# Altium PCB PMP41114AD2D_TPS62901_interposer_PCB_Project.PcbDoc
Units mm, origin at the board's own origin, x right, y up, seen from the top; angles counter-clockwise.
Board outline 10 x 15 mm, 2 copper layers (Top Layer, Bottom Layer), stack 1.575 mm thick; 10 components, 8 nets, 27 pads, 6 vias.
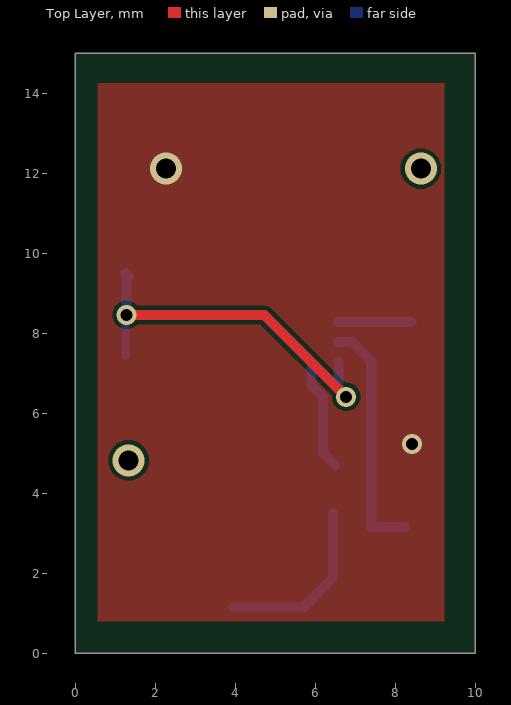
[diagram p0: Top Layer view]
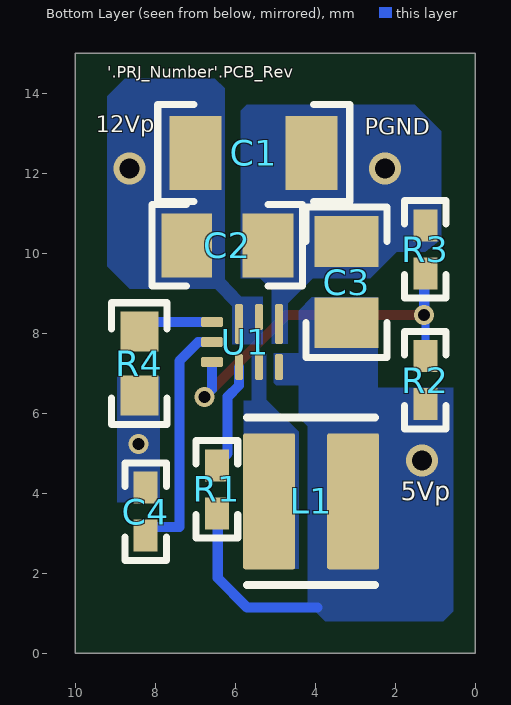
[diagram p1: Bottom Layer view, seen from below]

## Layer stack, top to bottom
Top Solder: solder mask 0.0102, Solder Resist, Dk 3.5
Top Layer: signal copper 0.0356
Dielectric1: core 1.5037, FR-4 High Tg, Dk 4.8
Bottom Layer: signal copper 0.0356
Bottom Solder: solder mask 0.0102, Solder Resist, Dk 3.5

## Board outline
0,0 0,15 10,15 10,0

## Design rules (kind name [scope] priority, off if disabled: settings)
AcuteAngle [All] p1: minimum=4.50000000000000E+0001 checktracksonly=FALSE
AssemblyTestPointUsage [All] p1: valid=2
BoardOutlineClearance [All] p1: gap=0.15 ignorepadtopadclearanceinfootprint=FALSE
Clearance Clearance_3 [All] p1: gap=0.1 ignorepadtopadclearanceinfootprint=FALSE
Clearance Clearance_2 [InNetClass('HV') vs InNetClass('HV')] p2: gap=1 ignorepadtopadclearanceinfootprint=TRUE
Clearance Clearance_1 [InNetClass('MV') vs Not InNetClass('MV')] p3: gap=0.2 ignorepadtopadclearanceinfootprint=TRUE
Clearance Clearance_Keepouts [((IsTrack Or IsArc) And Not InPoly) And IsFree and IsKeepOut vs ((IsTrack Or IsArc) And Not InPoly) And IsFree and IsKeepOut] p4: gap=0.3 ignorepadtopadclearanceinfootprint=FALSE
Clearance Clearance_BoardEdge_MountingHoles [OnCopper and InComponentClass('Mounting Holes') vs IsKeepOut] p5: gap=0.3 ignorepadtopadclearanceinfootprint=FALSE
Clearance Clearance_BoardEdge_Poly [OnCopper and InPoly vs IsKeepOut] p6: gap=0.635 ignorepadtopadclearanceinfootprint=FALSE except(0: Arc-Hole Track-Hole SMDPad-Hole THPad-Hole Via-Hole Fill-Hole Poly-Hole Region-Hole Text-Hole)
Clearance Clearance_BoardEdge [OnCopper and Not InComponentClass('Logo') and not InComponentClass('FiducialMark') and not InRegion(1000,500,4000,800) and Not IsKeepout vs IsKeepOut] p7: gap=1.905 ignorepadtopadclearanceinfootprint=FALSE except(0: Arc-Hole Track-Hole SMDPad-Hole THPad-Hole Via-Hole Fill-Hole Poly-Hole Region-Hole Text-Hole)
Clearance Clearance_Poly [InPolygon] p8: gap=0 ignorepadtopadclearanceinfootprint=FALSE
Clearance [All] p9: gap=0.2 ignorepadtopadclearanceinfootprint=FALSE except(0: Arc-SMDPad Arc-Hole Track-Hole SMDPad-Hole THPad-Hole Via-Hole Fill-Hole Poly-Hole Region-Hole Text-Hole; 0.1: Arc-Via Track-Via SMDPad-Via THPad-Via Via-Via; 0.127: Arc-Arc Arc-Track Arc-THPad Arc-Fill Track-Track Track-SMDPad Track-THPad Track-Fill SMDPad-SMDPad SMDPad-THPad SMDPad-Fill THPad-THPad THPad-Fill Via-Fill Fill-Fill)
ComponentClearance ComponentClearance_MountingHoles_FiducialMarks [InComponentClass('Mounting Holes') vs InComponentClass('FiducialMark')] p1: gap=0.508 collisioncheckmode=3 verticalgap=0.178 showdistances=FALSE
ComponentClearance ComponentClearance_Shunt [InComponentClass('Header') vs InComponentClass('Shunt')] p2: gap=0 collisioncheckmode=3 verticalgap=0 showdistances=FALSE
ComponentClearance ComponentClearance_Logo [InComponentClass('Logo')] p3: gap=0.127 collisioncheckmode=3 verticalgap=0.254 showdistances=FALSE
ComponentClearance ComponentClearance_ScrewToNut [(HasFootprint('KEYSTONE_4824')) vs (HasFootprint('Keystone_1903C'))] p4: gap=0 collisioncheckmode=3 verticalgap=0 showdistances=FALSE
ComponentClearance ComponentClearance_MountingHoles [InComponentClass('Mounting Holes')] p5: gap=0.508 collisioncheckmode=3 verticalgap=0.178 showdistances=FALSE
ComponentClearance ComponentClearance_SmallPassives [HasFootprint('0201*') or HasFootprint('0402*') or HasFootprint('0508') or HasFootprint('0603*') or HasFootprint('0612') or HasFootprint('0805*') or HasFootprint('0815*') or HasFootprint('0830*') or HasFootprint('1206*') or HasFootprint('1210*') or HasFootprint('1808*') or HasFootprint('1812*') or HasFootprint('1825*') or HasFootprint('2010*') or HasFootprint('2220*') or HasFootprint('2225*') or HasFootprint('2512*') or HasFootprint('2728*') or HasFootprint('3518*') vs HasFootprint('0201*') or HasFootprint('0402*') or HasFootprint('0508') or HasFootprint('0603*') or HasFootprint('0612') or HasFootprint('0805*') or HasFootprint('0815*') or HasFootprint('0830*') or HasFootprint('1206*') or HasFootprint('1210*') or HasFootprint('1808*') or HasFootprint('1812*') or HasFootprint('1825*') or HasFootprint('2010*') or HasFootprint('2220*') or HasFootprint('2225*') or HasFootprint('2512*') or HasFootprint('2728*') or HasFootprint('3518*')] p6: gap=0.127 collisioncheckmode=3 verticalgap=0.025 showdistances=FALSE
ComponentClearance ComponentClearance_THtoSMT [IsThruComponent vs IsSMTComponent] p7: gap=0.254 collisioncheckmode=3 verticalgap=0.178 showdistances=FALSE
ComponentClearance ComponentClearance_THtoTH [IsThruComponent vs IsThruComponent] p8: gap=0.254 collisioncheckmode=3 verticalgap=0.178 showdistances=FALSE
ComponentClearance [All] p9: gap=0.254 collisioncheckmode=3 verticalgap=0.178 showdistances=FALSE
DiffPairsRouting [All] p1: maxlimit=2.54 minlimit=0.254 mostfreqgap=0.254 toplayer_minwidth=0.381 toplayer_maxwidth=0.381 toplayer_prefwidth=0.381 bottomlayer_minwidth=0.381 bottomlayer_maxwidth=0.381 bottomlayer_prefwidth=0.381 maxuncoupledlength=25.4
FabricationTestPointUsage TestPointUsage [All] p1: valid=2 allowmultiple=FALSE
FabricationTestpoint Testpoint [All] p1: side=3 testpointundercomponent=TRUE minsize=1.016 maxsize=2.54 preferedsize=1.524 minholesize=0 maxholesize=1.016 preferedholesize=0.813 testpointgrid=0.025 allowsidetop=TRUE allowsidebottom=TRUE usegrid=TRUE gridtolerance=0
FanoutControl Fanout_LCC [IsLCC] p1: bgadir=Out bgaviamode=Centered fanoutstyle=Auto fanoutdirection=Alternating viagrid=0.025 // Fanout_LCC (Default Rule)
FanoutControl Fanout_BGA [IsBGA] p2: bgadir=Out bgaviamode=Centered fanoutstyle=Auto fanoutdirection=Alternating viagrid=0.025 // Fanout_BGA (Default Rule)
Height [All] p1: minheight=0 maxheight=76.2 prefheight=12.7
HoleSize [All] p1: absolutevalues=TRUE maxlimit=12.725 minlimit=0.178 maxpercent=80.000 minpercent=20.000
MinimumAnnularRing MinimumAnnularRing_ThermalPadVias [IsVia and InAnyComponent] p1: minimumring=0.15
MinimumAnnularRing [All] p2: minimumring=0.127
MinimumSolderMaskSliver MinimumSolderMaskSliver_Logo [InComponentClass('Logo') vs InComponentClass('Logo')] p1: minsoldermaskwidth=0.018
MinimumSolderMaskSliver [All] p2: minsoldermaskwidth=0.018
PlaneClearance [All] p1: clearance=0.2
PlaneConnect [All] p1: planeconnectstyle=Direct reliefexpansion=0.254 reliefentries=4 reliefconductorwidth=0.254 reliefairgap=0.254
PolygonConnect PolygonConnect_16 [All vs IsNamedPolygon('C106_2') Or IsNamedPolygon('Vout') Or IsNamedPolygon('IN+') Or IsNamedPolygon('Q203_5') Or IsNamedPolygon('IN+') Or IsNamedPolygon('Q201_5') Or IsNamedPolygon('C108_2') Or IsNamedPolygon('SGND') Or IsNamedPolygon('IN+') Or IsNamedPolygon('SGND') Or IsNamedPolygon('Q203_5') Or IsNamedPolygon('IN+') Or IsNamedPolygon('SGND') Or IsNamedPolygon('GND') Or IsNamedPolygon('C113_2') Or IsNamedPolygon('C107_2') Or IsNamedPolygon('C107_2') Or IsNamedPolygon('Vout') Or IsNamedPolygon('SIGNAL_LAYER_1_GND_P074') Or IsNamedPolygon('HV') Or IsNamedPolygon('C108_2') Or IsNamedPolygon('C103_2') Or IsNamedPolygon('Q201_5') Or IsNamedPolygon('Vout') Or IsNamedPolygon('C109_2') Or IsNamedPolygon('Q201_5') Or IsNamedPolygon('GND') Or IsNamedPolygon('C107_2') Or IsNamedPolygon('C102_1') Or IsNamedPolygon('GND') Or IsNamedPolygon('SGND') Or IsNamedPolygon('HS') Or IsNamedPolygon('Q203_5') Or IsNamedPolygon('Q201_5') Or IsNamedPolygon('Q203_5')] p1: connectstyle=Direct reliefconductorwidth=0.254 reliefentries=4 polygonreliefangle="90 Angle" airgapwidth=0.254
PolygonConnect PolygonConnect_15 [All vs IsNamedPolygon('C109_2') Or IsNamedPolygon('C107_2') Or IsNamedPolygon('HV') Or IsNamedPolygon('Q203_5') Or IsNamedPolygon('C107_2') Or IsNamedPolygon('HS') Or IsNamedPolygon('Q201_5') Or IsNamedPolygon('Q203_5') Or IsNamedPolygon('C106_2') Or IsNamedPolygon('C108_2') Or IsNamedPolygon('Vout') Or IsNamedPolygon('Q203_5') Or IsNamedPolygon('C108_2') Or IsNamedPolygon('C113_2') Or IsNamedPolygon('Q203_5') Or IsNamedPolygon('Q201_5') Or IsNamedPolygon('C107_2') Or IsNamedPolygon('C102_1') Or IsNamedPolygon('SGND') Or IsNamedPolygon('GND') Or IsNamedPolygon('SGND') Or IsNamedPolygon('GND') Or IsNamedPolygon('IN+') Or IsNamedPolygon('IN+') Or IsNamedPolygon('Q201_5') Or IsNamedPolygon('Q201_5') Or IsNamedPolygon('SGND') Or IsNamedPolygon('SGND') Or IsNamedPolygon('Vout') Or IsNamedPolygon('Vout') Or IsNamedPolygon('IN+') Or IsNamedPolygon('GND') Or IsNamedPolygon('IN+') Or IsNamedPolygon('GND')] p2: connectstyle=Direct reliefconductorwidth=0.254 reliefentries=4 polygonreliefangle="90 Angle" airgapwidth=0.254
PolygonConnect PolygonConnect_14 [All vs IsNamedPolygon('C106_2') Or IsNamedPolygon('C107_2') Or IsNamedPolygon('C107_2') Or IsNamedPolygon('C107_2') Or IsNamedPolygon('C102_1') Or IsNamedPolygon('Q203_5') Or IsNamedPolygon('Vout') Or IsNamedPolygon('Q203_5') Or IsNamedPolygon('Q203_5') Or IsNamedPolygon('Q201_5') Or IsNamedPolygon('C108_2') Or IsNamedPolygon('Q203_5') Or IsNamedPolygon('HS') Or IsNamedPolygon('HV') Or IsNamedPolygon('C108_2') Or IsNamedPolygon('Q201_5') Or IsNamedPolygon('C109_2') Or IsNamedPolygon('Q201_5') Or IsNamedPolygon('Q201_5') Or IsNamedPolygon('C113_2')] p3: connectstyle=Direct reliefconductorwidth=0.254 reliefentries=4 polygonreliefangle="90 Angle" airgapwidth=0.254
PolygonConnect PolygonConnect_13 [All vs IsNamedPolygon('C102_1') Or IsNamedPolygon('HV') Or IsNamedPolygon('C107_2') Or IsNamedPolygon('C109_2') Or IsNamedPolygon('C107_2') Or IsNamedPolygon('C108_2') Or IsNamedPolygon('C106_2') Or IsNamedPolygon('C108_2') Or IsNamedPolygon('C113_2') Or IsNamedPolygon('C107_2')] p4: connectstyle=Direct reliefconductorwidth=0.254 reliefentries=4 polygonreliefangle="90 Angle" airgapwidth=0.254
PolygonConnect PolygonConnect_12 [All vs IsNamedPolygon('C107_2') Or IsNamedPolygon('C113_2') Or IsNamedPolygon('C106_2') Or IsNamedPolygon('C107_2') Or IsNamedPolygon('C107_2') Or IsNamedPolygon('C102_1')] p5: connectstyle=Direct reliefconductorwidth=0.254 reliefentries=4 polygonreliefangle="90 Angle" airgapwidth=0.254
PolygonConnect PolygonConnect_11 [All vs IsNamedPolygon('C106_2') Or IsNamedPolygon('C102_1') Or IsNamedPolygon('C107_2') Or IsNamedPolygon('C107_2') Or IsNamedPolygon('C107_2')] p6: connectstyle=Direct reliefconductorwidth=0.254 reliefentries=4 polygonreliefangle="90 Angle" airgapwidth=0.254
PolygonConnect PolygonConnect_10 [All vs IsNamedPolygon('C106_2')] p7: connectstyle=Direct reliefconductorwidth=0.254 reliefentries=4 polygonreliefangle="90 Angle" airgapwidth=0.254
PolygonConnect PolygonConnect_9 [All vs IsNamedPolygon('C11_1') Or IsNamedPolygon('Vin') Or IsNamedPolygon('Vin') Or IsNamedPolygon('5V') Or IsNamedPolygon('D6_2') Or IsNamedPolygon('Q3_3') Or IsNamedPolygon('GND2') Or IsNamedPolygon('GND2') Or IsNamedPolygon('GND') Or IsNamedPolygon('Q3_4') Or IsNamedPolygon('12V5') Or IsNamedPolygon('GND') Or IsNamedPolygon('12V5') Or IsNamedPolygon('D3_1')] p8: connectstyle=Direct reliefconductorwidth=0.254 reliefentries=4 polygonreliefangle="90 Angle" airgapwidth=0.254
PolygonConnect PolygonConnect_8 [All vs IsNamedPolygon('C11_1') Or IsNamedPolygon('Vin') Or IsNamedPolygon('12V5') Or IsNamedPolygon('Q3_3') Or IsNamedPolygon('GND2') Or IsNamedPolygon('GND2') Or IsNamedPolygon('5V') Or IsNamedPolygon('Q3_4') Or IsNamedPolygon('12V5')] p9: connectstyle=Direct reliefconductorwidth=0.254 reliefentries=4 polygonreliefangle="90 Angle" airgapwidth=0.254
PolygonConnect PolygonConnect_7 [All vs IsNamedPolygon('GND2') Or IsNamedPolygon('GND2') Or IsNamedPolygon('5V') Or IsNamedPolygon('12V5') Or IsNamedPolygon('12V5') Or IsNamedPolygon('C11_1')] p10: connectstyle=Direct reliefconductorwidth=0.254 reliefentries=4 polygonreliefangle="90 Angle" airgapwidth=0.254
PolygonConnect PolygonConnect_6 [All vs IsNamedPolygon('GND2') Or IsNamedPolygon('SGND') Or IsNamedPolygon('GND1') Or IsNamedPolygon('C901_1') Or IsNamedPolygon('SGND') Or IsNamedPolygon('GND2') Or IsNamedPolygon('GND1')] p11: connectstyle=Direct reliefconductorwidth=0.254 reliefentries=4 polygonreliefangle="90 Angle" airgapwidth=0.254
PolygonConnect PolygonConnect_5 [All vs IsNamedPolygon('GND1') Or IsNamedPolygon('GND1')] p12: connectstyle=Direct reliefconductorwidth=0.254 reliefentries=4 polygonreliefangle="90 Angle" airgapwidth=0.254
PolygonConnect PolygonConnect_4 [All vs IsNamedPolygon('C21_1') Or IsNamedPolygon('C5_1') Or IsNamedPolygon('C12_2') Or IsNamedPolygon('C2_2') Or IsNamedPolygon('C13_1') Or IsNamedPolygon('C28_1') Or IsNamedPolygon('C6_1') Or IsNamedPolygon('GND') Or IsNamedPolygon('GND2') Or IsNamedPolygon('C14_1') Or IsNamedPolygon('C13_1') Or IsNamedPolygon('Q1_3') Or IsNamedPolygon('C14_1') Or IsNamedPolygon('C5_1') Or IsNamedPolygon('GND2') Or IsNamedPolygon('C28_1') Or IsNamedPolygon('D5_2') Or IsNamedPolygon('D6_2') Or IsNamedPolygon('D2_1') Or IsNamedPolygon('C12_2') Or IsNamedPolygon('D2_1') Or IsNamedPolygon('C4_1') Or IsNamedPolygon('C4_1') Or IsNamedPolygon('C2_2') Or IsNamedPolygon('GND') Or IsNamedPolygon('C33_1') Or IsNamedPolygon('C9_1')] p13: connectstyle=Direct reliefconductorwidth=0.254 reliefentries=4 polygonreliefangle="90 Angle" airgapwidth=0.254
PolygonConnect PolygonConnect_3 [All vs IsNamedPolygon('C28_1') Or IsNamedPolygon('C12_2') Or IsNamedPolygon('C28_1') Or IsNamedPolygon('C9_1') Or IsNamedPolygon('D5_2') Or IsNamedPolygon('C12_2') Or IsNamedPolygon('C2_2') Or IsNamedPolygon('C14_1') Or IsNamedPolygon('C4_1') Or IsNamedPolygon('C14_1') Or IsNamedPolygon('D6_2') Or IsNamedPolygon('GND2') Or IsNamedPolygon('Q1_3') Or IsNamedPolygon('C5_1') Or IsNamedPolygon('D2_1') Or IsNamedPolygon('C4_1') Or IsNamedPolygon('C13_1') Or IsNamedPolygon('C5_1') Or IsNamedPolygon('C13_1') Or IsNamedPolygon('C33_1') Or IsNamedPolygon('D2_1') Or IsNamedPolygon('GND') Or IsNamedPolygon('GND') Or IsNamedPolygon('GND2') Or IsNamedPolygon('C2_2') Or IsNamedPolygon('C6_1') Or IsNamedPolygon('C21_1')] p14: connectstyle=Direct reliefconductorwidth=0.254 reliefentries=4 polygonreliefangle="90 Angle" airgapwidth=0.254
PolygonConnect PolygonConnect_2 [All vs IsNamedPolygon('C21_1') Or IsNamedPolygon('C4_1') Or IsNamedPolygon('D5_2') Or IsNamedPolygon('C5_1') Or IsNamedPolygon('C14_1') Or IsNamedPolygon('C13_1') Or IsNamedPolygon('C4_1') Or IsNamedPolygon('C33_1') Or IsNamedPolygon('C12_2') Or IsNamedPolygon('D2_1') Or IsNamedPolygon('C2_2') Or IsNamedPolygon('C28_1') Or IsNamedPolygon('C12_2') Or IsNamedPolygon('D2_1') Or IsNamedPolygon('C5_1') Or IsNamedPolygon('Q1_3') Or IsNamedPolygon('GND') Or IsNamedPolygon('D6_2') Or IsNamedPolygon('C6_1') Or IsNamedPolygon('C2_2') Or IsNamedPolygon('C14_1') Or IsNamedPolygon('C28_1') Or IsNamedPolygon('C13_1') Or IsNamedPolygon('C9_1') Or IsNamedPolygon('GND')] p15: connectstyle=Direct reliefconductorwidth=0.254 reliefentries=4 polygonreliefangle="90 Angle" airgapwidth=0.254
PolygonConnect PolygonConnect_1 [All vs IsNamedPolygon('C28_1') Or IsNamedPolygon('D5_2') Or IsNamedPolygon('C5_1') Or IsNamedPolygon('C5_1') Or IsNamedPolygon('D2_1') Or IsNamedPolygon('C21_1') Or IsNamedPolygon('C9_1') Or IsNamedPolygon('C4_1') Or IsNamedPolygon('C14_1') Or IsNamedPolygon('C28_1') Or IsNamedPolygon('C6_1') Or IsNamedPolygon('C12_2') Or IsNamedPolygon('C33_1') Or IsNamedPolygon('C4_1') Or IsNamedPolygon('C13_1') Or IsNamedPolygon('C12_2') Or IsNamedPolygon('D6_2') Or IsNamedPolygon('C2_2') Or IsNamedPolygon('C14_1') Or IsNamedPolygon('D2_1') Or IsNamedPolygon('C2_2') Or IsNamedPolygon('C13_1')] p16: connectstyle=Direct reliefconductorwidth=0.254 reliefentries=4 polygonreliefangle="90 Angle" airgapwidth=0.254
PolygonConnect [All] p17: connectstyle=Direct reliefconductorwidth=0.254 reliefentries=4 polygonreliefangle="90 Angle" airgapwidth=0.254
RoutingVias ThermalPadVias [IsVia and not InNet('SGND')and not InNet('Vout')] p1: holewidth=0.2 width=0.5 viastyle="Through Hole" minholewidth=0.2 minwidth=0.5 maxholewidth=1 maxwidth=2
RoutingVias [IsVia and not InNet('SGND')and not InNet('Vout')] p2: holewidth=0.406 width=0.864 viastyle="Through Hole" minholewidth=0.2 minwidth=0.508 maxholewidth=1.016 maxwidth=1.651
SilkToBoardRegionClearance [Not ((IsComment or IsDesignator) And (Hide <> 'False')) and not InRegion(1000,500,4000,800)] p1:
SilkToSilkClearance SilkToSilkClearance_Pb-FreeLogo [(HasFootprint('Pb-Free_Overlay_Medium') OR HasFootprint('Pb-Free_Overlay_Small')) vs (HasFootprint('Pb-Free_Overlay_Medium') OR HasFootprint('Pb-Free_Overlay_Small'))] p1: silktosilkclearance=0
SilkToSilkClearance [All] p2: silktosilkclearance=0
SilkToSolderMaskClearance "Silk to Solder Mask Opening" [All] p1: minsilkscreentomaskgap=0 clearancetoexposedcopper=FALSE
SolderMaskExpansion [All] p1: expansion=0.05 istentingtop=FALSE
SupplyNets "Schematic Supply Nets_1" [InNet('PGND')] p1: voltage=0.000
UnpouredPolygon [All] p1: allowunpoured=TRUE allowshelved=TRUE
Width [All] p1: maxlimit=2.54 minlimit=0.152 preferedwidth=0.2 checkconnectedcopper=TRUE
14 further rules are at their usual default settings.

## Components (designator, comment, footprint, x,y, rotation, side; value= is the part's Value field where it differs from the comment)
C1 "C3216X7R1A106M160AC" 1206 5.54,12.51 r180 bottom value=10uF
C2 "C0805C105K3RACTU" 0805_HV 6.2,10.2 r180 bottom value=1uF
C3 "CL21A226KQQNNNE" 0805_HV 3.22,9.28 r90 bottom value=22uF
C4 "GRM155R72A332KA01D" 0402 8.24,3.54 r90 bottom value=3300pF
L1 "74438336022" FP-74438336010_SMD2-MFG 4.105,3.8 r180 bottom
R1 "RC0402FR-07100KL" 0402 6.46,4.1 r270 bottom value=100k
R2 "RC0402FR-07100KL" 0402 1.25,6.83 r270 bottom value=100k
R3 "CRCW040276K8FKED" 0402 1.25,10.1 r270 bottom value=76.8k
R4 "CRCW0603118KFKEA" 0603 8.4,7.24 r90 bottom value=118k
U1 "TPS62901RPJR" RPJ0009A 5.659,7.781 r90 bottom

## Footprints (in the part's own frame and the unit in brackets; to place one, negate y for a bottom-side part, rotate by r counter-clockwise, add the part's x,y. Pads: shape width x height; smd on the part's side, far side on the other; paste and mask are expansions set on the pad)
0402 [mm] "0402 from SM-752 data"
  rect 0.8x0.6 smd: 1(-0.6,0) 2(0.6,0)
  silkscreen extent -1.22,-0.52 1.22,0.52, body extent -0.55,-0.3 0.55,0.3, height 0.6
0603 [mm] "0603 from SM-752 data"
  rect 1x0.95 smd: 1(-0.8,0) 2(0.8,0)
  silkscreen extent -1.52,-0.69 1.52,0.69, body extent -0.87,-0.47 0.87,0.47, height 1
0805_HV [mil] "0805 with 30mil clearance between pads"
  rect 50x63 smd: 1(-40,0) 2(40,0)
  silkscreen extent -74,-40 74,40, body extent -43,-29 43,29, height 57
1206 [mm] "1206 from SM-752 data"
  rect 1.3x1.85 smd: 1(-1.45,0) 2(1.45,0)
  silkscreen extent -2.4,-1.21 2.4,1.21, body extent -1.7,-0.9 1.7,0.9, height 1.35
FP-74438336010_SMD2-MFG [mm]
  rrect8% 1.3x3.4 smd paste+0 mask+0: 1(-1.05,0) 2(1.05,0)
  silkscreen extent -1.6,-2.1 1.6,2.1, body extent -1.5,-1.5 1.5,1.5, height 2
RPJ0009A [mm] "VQFN-HR-9"
  rrect50% 0.65x0.2 smd: 1(-0.625,0.25) 2(-0.625,-0.25) 3(-0.625,-0.75) 5(0.625,-0.25)
  rrect50% 1x0.2 smd: 4(0.45,-0.75) 6(0.45,0.25)
  rrect40% 0.25x0.55 smd: 7(0.5,0.925) 8(0,0.925) 9(-0.5,0.925)
  body extent -0.8,-1.05 0.8,1.05, height 1

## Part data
C1: library part CMP-0008689-2, "CAP, CERM, 10 uF, 10 V, +/- 20%, X7R, 1206", Cap_Case=1206, Manufacturer=TDK, Supplier Part Number 1=445-1602-1-ND, TempCo=X7R, Tolerance_%=20%, Value1="0.0046 ohm", Value2=10V, ValueDisplayed=10uF
C2: library part CMP-0007728-2, "CAP, CERM, 1 uF, 25 V, +/- 10%, X7R, 0805", Cap_Case=0805, Manufacturer=Kemet, Supplier Part Number 1=399-8004-1-ND, TempCo=X7R, Tolerance_%=10%, Value1=Unknown, Value2=25V, ValueDisplayed=1uF
C3: library part CMP-0007989-2, "CAP, CERM, 22 uF, 6.3 V, +/- 10%, X5R, 0805", Cap_Case=0805, Manufacturer="Samsung Electro-Mechanics", TempCo=X5R, Tolerance_%=10%, Value1=Unknown, Value2=6.3V, ValueDisplayed=22uF
C4: library part CMP-0006708-2, "CAP, CERM, 3300 pF, 100 V, +/- 10%, X7R, 0402", Cap_Case=0402, Manufacturer=MuRata, Supplier Part Number 1=GRM155R72A332KA01D-ND, TempCo=X7R, Tolerance_%=10%, Value1=Unknown, Value2=100V, ValueDisplayed=3300pF
L1: library part CMP-0087867-1, "2.2µH Shielded Molded Inductor 2.4A 67mOhm Max 2-SMD", Manufacturer="Wurth Electronics"
R1 R2: library part CMP-0026721-1, "RES, 100 k, 1%, 0.0625 W, 0402", Manufacturer="Yageo America", Power_W=62.5mW, Supplier Part Number 1=311-100KLRCT-ND, TempCo="100 ppm/C", Tolerance_%=1%, Value2=0.0625W, Value_Code=100k
R3: library part CMP-0026547-2, "RES, 76.8 k, 1%, 0.063 W, AEC-Q200 Grade 0, 0402", Manufacturer=Vishay-Dale, Power_W=63mW, Supplier Part Number 1=541-76.8KLCT-ND, TempCo="100 ppm/C", Tolerance_%=1%, Value2=0.063W, Value_Code=76k8, ValueDisplayed=76.8k
R4: library part CMP-0022014-4, "RES, 118 k, 1%, 0.1 W, AEC-Q200 Grade 0, 0603", Manufacturer=Vishay-Dale, Power_W=100mW, Supplier Part Number 1=541-118KHCT-ND, TempCo="100 ppm/C", Tolerance_%=1%, Value2=0.1W, Value_Code=118k
U1: library part CMP-0084864-4, "2.9-V to 18-V, 4-A Synchronous Buck Converters, RPJ0009A (VQFN-HR-9)", Alternate Manufacturer="Texas Instruments", Alternate PartNumber=TPS62901RPJT

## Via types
v1: diameter 0.5, hole 0.3, Top Layer to Bottom Layer, 3 vias
v2: diameter 0.8, hole 0.5, Top Layer to Bottom Layer, 3 vias

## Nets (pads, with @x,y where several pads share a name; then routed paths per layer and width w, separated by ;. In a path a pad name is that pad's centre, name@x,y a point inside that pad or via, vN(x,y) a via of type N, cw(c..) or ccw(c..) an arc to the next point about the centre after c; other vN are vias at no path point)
5Vp: C3.1 L1.2 R1.2 R2.2 U1.3 | length 4.4
  Bottom Layer w0.254: 3.951,1.143 5.702,1.143 6.44,1.881 R1.2@6.44,3.5
  other v2: 1.331,4.824
12Vp: C1.1 C2.1 U1.5 U1.6
  other v2: 8.641,12.12
NetC4_1: C4.1 U1.8 | length 6
  Bottom Layer w0.254: U1.8 6.926,7.781 7.399,7.308 7.399,5.469 7.399,3.16 C4.1@8.24,3.16
NetL1_1: L1.1 U1.2
NetR1_1: R1.1 U1.1 | length 2.7
  Bottom Layer w0.254: U1.1 5.909,6.696 6.192,6.412 6.192,6.173 6.192,5.001 R1.1@6.493,4.7
NetR2_1: R2.1 R3.2 U1.9 | length 9.4
  Top Layer w0.254: v1(1.28,8.46) 4.721,8.46 v1(6.769,6.412)
  Bottom Layer w0.2: R2.1 1.25,8.43 v1(1.28,8.46)
  Bottom Layer w0.254: R3.2 1.336,9.414 1.278,9.357 1.278,8.462 v1(1.28,8.46) ; U1.9 6.584,6.598 v1(6.769,6.412)
NetR4_2: R4.2 U1.7 | length 1.8
  Bottom Layer w0.254: U1.7 R4.2@8.4,8.281
PGND: C1.2 C2.2 C3.2 C4.2 R3.1 R4.1 U1.4
  other v1: 8.419,5.236
  other v2: 2.263,12.12

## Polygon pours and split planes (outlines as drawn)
PGND on Bottom Layer "BOTTOM_LAYER_PGND_P000" (solid, remove dead copper, pour order 0): 5.709,13.716 1.516,13.716 0.85,13.05 0.85,10.357 1.252,10.037 1.963,10.037 2.623,9.377 4.059,9.377 4.685,8.751 4.685,7.741 5.085,7.741 5.085,9.085 5.377,9.377 5.86,9.377 5.86,13.566
12Vp on Bottom Layer "BOTTOM_LAYER_12VP_P001" (solid, remove dead copper, pour order 1): 9.2,13.93 8.76,14.37 6.51,14.37 6.27,14.13 6.27,9.357 5.851,8.913 5.312,8.913 5.312,7.732 6.076,7.732 6.076,8.68 6.508,9.112 8.641,9.112 9.2,9.671
PGND on Bottom Layer "BOTTOM_LAYER_PGND_P003" (solid, remove dead copper, pour order 3): 7.89,6.917 7.89,3.775 8.948,3.775 8.948,6.917
5Vp on Bottom Layer "BOTTOM_LAYER_5VP_P006" (solid, remove dead copper, pour order 6): 4.428,7.497 5.034,7.497 5.034,6.763 4.979,6.708 4.368,6.708 4.368,7.451 4.4,7.483 4.414,7.483
NetL1_1 on Bottom Layer "BOTTOM_LAYER_NETL1_1_P004" (solid, remove dead copper, pour order 4): 5.223,7.479 5.223,6.345 4.42,5.542 4.42,2.112 5.745,2.112 5.785,2.152 5.785,6.309 5.588,6.309 5.588,7.479
5Vp on Bottom Layer "BOTTOM_LAYER_5VP_P002" (solid, remove dead copper, pour order 2): 4.094,8.896 2.437,8.896 2.442,6.636 0.55,6.636 0.55,1.05 0.8,0.8 3.746,0.8 4.189,1.243 4.189,5.671 4.42,5.901 4.42,8.57
PGND on Top Layer "TOP_LAYER_PGND_P005" (solid, remove dead copper, pour order 5): 0.559,14.25 9.221,14.25 9.221,0.8 0.559,0.8

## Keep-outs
Keep-Out Layer:
  text ".Layer_Name" at 14.656,-21.806 h1.52

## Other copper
Top Layer:
  text ".Layer_Name" at 14.656,-21.806 h1.52
Bottom Layer:
  text ".Layer_Name" at 14.656,-21.806 h1.52

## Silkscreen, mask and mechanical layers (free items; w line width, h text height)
Top Overlay:
  text ".Layer_Name" at 14.656,-21.806 h1.52
Bottom Overlay:
  text "'.PRJ_Number'.PCB_Rev" at 9.2,14.29 h0.5
  text "12Vp" at 9.495,12.887 h0.7
  text "PGND" at 2.768,12.826 h0.7
  text "5Vp" at 1.859,3.658 h0.8
  text ".Layer_Name" at 14.656,-21.806 h1.52
Top Paste:
  text ".Layer_Name" at 14.656,-21.806 h1.52
Bottom Paste:
  text ".Layer_Name" at 14.656,-21.806 h1.52
Top Solder:
  text ".Layer_Name" at 14.656,-21.806 h1.52
  text ".Layer_Name" at 14.656,-21.806 h1.52
Bottom Solder:
  text ".Layer_Name" at 14.656,-21.806 h1.52
Drill Guide:
  text ".Layer_Name" at 14.656,-21.806 h1.52
M1 Board Outline:
  the board outline again, w0.254
  text ".Layer_Name" at 14.656,-21.806 h1.52
M2 Board Dimensions:
  rectangle: 3.175,-10.16 12.7,-6.985
  rectangle: 0,-6.985 3.175,-3.81
  lines w0.178: 0,-6.985 25.4,-6.985 ; 3.175,-10.16 3.175,-3.81 ; 6.35,-10.16 6.35,-3.81 ; 12.7,-10.16 12.7,-3.81 ; 19.05,-10.16 19.05,-3.81 ; 0,-10.16 0,-3.81 25.4,-3.81 25.4,-10.16 0,-10.16
  text ".Layer_Name" at 14.656,-21.806 h1.52
M3 3D STEP Top:
  text ".Layer_Name" at 14.656,-21.806 h1.52
M4 3D STEP Bottom:
  text ".Layer_Name" at 14.656,-21.806 h1.52
M5 Assembly Top:
  lines w0.254: -7.417,-23.626 160.223,-23.626 ; -7.417,-18.462 160.274,-18.462 ; -7.417,-13.297 -7.417,-28.791 94.31,-28.791 160.274,-28.791 160.274,-13.297 -7.404,-13.297 -7.404,-28.791 32.614,-28.791 ; 55.194,-28.791 55.194,-13.297 ; 87.376,-18.462 87.376,-13.297 ; 108.712,-18.462 108.712,-13.297 ; 124.511,-28.956 124.511,-23.804
  text "COMPONENTS MARKED 'DNP' SHOULD NOT BE POPULATED." at 29.299,-8.09 h1.52
  text "ASSEMBLY VARIANT:" at 29.286,-11.024 h1.52
  text ".VariantName" at 55.601,-11.024 h1.52
  text "PCB VIEWED FROM TOP SIDE" at -5.804,-16.654 h1.52
  text "BOARD #:" at 57.099,-16.654 h1.52
  text ".PRJ_Number" at 70.955,-16.654 h1.52
  text "REV:" at 92.405,-16.654 h1.52
  text ".PCB_Rev" at 99.809,-16.654 h1.52
  text "SVN REV:" at 113.69,-16.654 h1.52
  text ".VersionControl_RevNumber" at 126.543,-16.654 h1.52
  text "PLOT NAME =" at -5.804,-27.034 h1.52
  text ".plot_File_Name" at 14.656,-27.034 h1.52
  text "GENERATED    :" at 57.15,-27.034 h1.52
  text ".Print_Date" at 79.235,-27.034 h1.52
  text ".Print_Time" at 97.752,-27.034 h1.52
  text "TEXAS INSTRUMENTS" at 129.87,-27.034 h1.52
M6 Assembly Bottom:
  lines w0.254: -7.429,-18.474 160.261,-18.474 ; -7.379,-23.639 160.261,-23.639 ; 28.334,-28.969 28.334,-23.817 ; 44.133,-18.474 44.133,-13.31 ; 65.468,-18.474 65.468,-13.31 ; 97.65,-28.804 97.65,-13.31 ; 120.231,-28.804 160.249,-28.804 160.249,-13.31 -7.429,-13.31 -7.429,-28.804 58.534,-28.804 160.261,-28.804 160.261,-13.31
  text "COMPONENTS MARKED 'DNP' SHOULD NOT BE POPULATED." at 154.991,-8.077 h1.52
  text ".VariantName" at 128.473,-11.024 h1.52
  text "ASSEMBLY VARIANT:" at 154.864,-11.024 h1.52
  text ".VersionControl_RevNumber" at 26.302,-16.667 h1.52
  text "SVN REV:" at 39.154,-16.667 h1.52
  text ".PCB_Rev" at 53.035,-16.667 h1.52
  text "REV:" at 60.439,-16.667 h1.52
  text ".PRJ_Number" at 81.89,-16.667 h1.52
  text "BOARD #:" at 95.745,-16.667 h1.52
  text "PCB VIEWED FROM BOTTOM SIDE" at 158.648,-16.667 h1.52
  text "TEXAS INSTRUMENTS" at 22.974,-27.047 h1.52
  text ".Print_Time" at 55.093,-27.047 h1.52
  text ".Print_Date" at 73.609,-27.047 h1.52
  text "GENERATED    :" at 95.694,-27.047 h1.52
  text ".plot_File_Name" at 138.189,-27.047 h1.52
  text "PLOT NAME =" at 158.648,-27.047 h1.52
M9 Title Sheet:
  drawing of 63 lines, arcs and shapes, not listed
  text "1" at 35.293,466.75 h1.78
  text "2" at 136.766,466.75 h1.78
  text "3" at 238.239,466.75 h1.78
  text "4" at 339.865,466.75 h1.78
  text "5" at 441.423,466.75 h1.78
  text "6" at 542.98,466.75 h1.78
  text "7" at 644.623,466.75 h1.78
  text "8" at 746.096,466.75 h1.78
  text "A" at -11.874,405.841 h1.78
  text "A" at 793.305,405.841 h1.78
  text "B" at -11.874,278.841 h1.78
  text "B" at 793.305,278.841 h1.78
  text "C" at -11.874,151.841 h1.78
  text "C" at 793.305,151.841 h1.78
  text "D" at -11.874,24.841 h1.78
  text "D" at 793.305,24.841 h1.78
  text "PROJECT TITLE:" at 714.947,6.823 h1.14
  text ".PRJ_Title" at 716.216,3.436 h1.78
  text "DESIGNED FOR:" at 714.947,-0.823 h1.14
  text ".PRJ_Customer" at 716.216,-4.379 h1.78
  text "FILE NAME:" at 714.947,-8.443 h1.14
  text ".PCB_File_Name_No_Path" at 716.216,-11.491 h1.78
  text "Texas Instruments (TI) and/or its licensors do not warrant the accuracy or completeness of this specification" at 588.721,-15.601 h1.14
  text "ENGINEER:" at 714.947,-15.809 h1.14
  text "LAYOUT BY:" at 753.173,-15.809 h1.14
  text "or any information contained therein. TI and/or its licensors do not warrant that this design will meet" at 587.579,-18.463 h1.14
  text ".PRJ_Engineer" at 716.216,-19.746 h1.78
  text ".PCB_Layout" at 754.456,-19.746 h1.78
  text "the specifications, will be suitable for your application or fit for any particular purpose, or will operate in" at 587.579,-21.325 h1.14
  text ".Layer_Name" at 14.656,-21.806 h1.52
  text "ALTIUM DESIGNER VERSION:" at 753.173,-23.683 h1.14
  text "an implementation. TI and/or its licensors do not warrant that the design is production worthy. You should" at 587.579,-24.187 h1.14
  text "completely validate and test your design implementation to confirm the system functionality for your application." at 588.721,-27.048 h1.14
  text ".print_Scale" at 716.216,-27.069 h1.78
  text ".Application_BuildNumber" at 754.456,-27.069 h1.78
  text "1" at 35.293,-33.503 h1.78
  text "2" at 136.766,-33.503 h1.78
  text "3" at 238.239,-33.503 h1.78
  text "4" at 339.865,-33.503 h1.78
  text "5" at 441.423,-33.503 h1.78
  text "6" at 542.98,-33.503 h1.78
  text "7" at 644.623,-33.503 h1.78
  text "8" at 746.096,-33.503 h1.78
M10 Fab Notes:
  drawing of 189 lines, arcs and shapes, not listed
  text "DESIGN INFORMATION" at 741.376,161.675 h1.52
  text "MIN. TRACK WIDTH:" at 725.004,158.319 h1.52
  text "8" at 752.848,158.32 h1.52
  text "MIL" at 756.779,158.319 h1.52
  text "MIN. CLEARANCE:" at 725.004,155.167 h1.52
  text "7.874" at 748.5,155.167 h1.52
  text "MIL" at 756.779,155.167 h1.52
  text "MIN. VIA PAD SIZE:" at 725.004,152.014 h1.52
  text "24" at 752.087,152.014 h1.52
  text "MIL" at 756.779,152.014 h1.52
  text "0.05mm (2MIL)" at 742.657,148.714 h1.52
  text "MINIMUM ANNULAR RING" at 716.641,148.506 h1.52
  text "EXTERNAL" at 760.64,148.506 h1.52
  text "PER" at 721.721,145.708 h1.52
  text "IPC-D-275 CLASS 2 LEVEL C" at 727.309,145.708 h1.52
  text "MIL, HOLES" at 765.11,143.156 h1.52
  text "+/-" at 755.142,142.938 h1.52
  text "+/-" at 776.834,142.938 h1.52
  text "REGISTRATION TOLERANCES:" at 716.641,142.911 h1.52
  text "METAL" at 747.116,142.911 h1.52
  text "5" at 761.751,142.911 h1.52
  text "3" at 782.909,142.911 h1.52
  text "MIL" at 785.862,142.911 h1.52
  text "HOLE SIZE TOLERANCE (UNLESS OTHERWISE SPECIFIED):" at 716.641,140.414 h1.52
  text "+/-" at 776.834,140.341 h1.52
  text "3" at 782.909,140.314 h1.52
  text "MIL" at 785.862,140.314 h1.52
  text "MATERIAL:" at 714.742,136.818 h1.52
  text "FR-4 High Tg" at 739.798,133.553 h1.52
  text "X" at 736.129,133.35 h1.52
  text "FR-4" at 725.436,133.235 h1.52
  text "OTHER" at 763.231,133.235 h1.52
  text "62 MIL (1.6mm) +/-10%" at 733.566,129.602 h1.52
  text "X" at 730.516,129.54 h1.52
  text "THICKNESS:" at 716.641,129.394 h1.52
  text "OTHER" at 766.203,129.394 h1.52
  text "TOLERANCE:" at 716.641,125.88 h1.52
  text "X" at 738.187,125.88 h1.52
  text "ANSI IPC-6012 TYPE 3 CLASS 2" at 742.708,125.88 h1.52
  text "OTHER +/-" at 742.708,122.218 h1.52
  text "BOW & TWIST:" at 716.641,118.53 h1.52
  text "X" at 738.187,118.53 h1.52
  text "ANSI IPC-6012 TYPE 3 CLASS 2" at 742.708,118.53 h1.52
  text "OTHER +/-" at 742.708,114.804 h1.52
  text "DRILLING:" at 714.742,111.486 h1.52
  text "NC_DRILL FILES" at 759.472,108.815 h1.52
  text "REFERENCE:" at 716.641,108.715 h1.52
  text "X" at 733.335,108.712 h1.52
  text "AS SHOWN" at 737.856,108.715 h1.52
  text "X" at 756.221,108.715 h1.52
  text "OTHER" at 767.041,105.101 h1.52
  text "PTH COPPER THICKNESS:" at 716.633,105.012 h1.52
  text "X" at 745.57,105.012 h1.52
  text "20-30 um" at 748.821,105.012 h1.52
  text "BOARD FINISH:" at 714.742,101.263 h1.52
  text "SILKSCREEN:" at 718.685,98.466 h1.52
  text "X" at 743.013,98.466 h1.52
  text "TOP" at 745.984,98.466 h1.52
  text "X" at 755.967,98.466 h1.52
  text "BOTTOM" at 758.964,98.466 h1.52
  text "SILKSCREEN COLOR:" at 718.685,94.524 h1.52
  text "X" at 742.987,94.524 h1.52
  text "WHITE" at 745.984,94.524 h1.52
  text "OTHER" at 758.964,94.524 h1.52
  text "X" at 746.315,90.88 h1.52
  text "GREEN" at 749.312,90.88 h1.52
  text "OTHER" at 765.009,90.88 h1.52
  text "SOLDER RESIST COLOR:" at 718.685,90.706 h1.52
  text "X" at 746.315,86.962 h1.52
  text "MATTE" at 749.312,86.962 h1.52
  text "SEMI-GLOSS" at 764.997,86.946 h1.52
  text "IMMERSION GOLD (ENIG)" at 741.692,82.574 h1.52
  text "ENEPIG" at 775.665,82.39 h1.52
  text "SURFACE FINISH:" at 714.742,82.365 h1.52
  text "X" at 737.171,82.365 h1.52
  text "IMM. TIN/SILVER OR EQUIV" at 723.113,78.877 h1.52
  text "OTHER" at 759.472,78.777 h1.52
  text "ARRAY/PANEL:" at 714.742,74.831 h1.52
  text "CUT AND TRIM PER M1 BOARD OUTLINE" at 741.692,74.622 h1.52
  text "N.C. ROUTE" at 741.692,71.168 h1.52
  text "X" at 759.167,71.168 h1.52
  text "V. SCORE" at 763.688,71.168 h1.52
  text "CERTIFICATION:" at 714.742,67.888 h1.52
  text "MATERIALS AND WORKMANSHIP FOR ALL PCBS" at 733.157,67.888 h1.52
  text "TO MEET OR EXCEED THE REQUIREMENTS OF:" at 733.157,65.499 h1.52
  text "X" at 723.95,62.232 h1.52
  text "ANSI IPC-A-600F CLASS ->" at 727.201,62.232 h1.52
  text "X" at 769.06,62.232 h1.52
  text "2" at 771.854,62.232 h1.52
  text "1" at 763.853,62.194 h1.52
  text "3" at 780.846,62.194 h1.52
  text "X" at 744.575,58.481 h1.52
  text "RoHS" at 747.826,58.481 h1.52
  text "OTHER" at 764.194,58.481 h1.52
  text "PER ORDER" at 774.279,58.481 h1.52
  text "ALL BOARDS MUST MEET OR EXCEED UL94-V0 REQUIREMENTS." at 715.442,54.574 h1.52
  text "PCB MUST BEAR THE UL94V-0 UL REGISTERED MATERIAL ID NUMBER" at 715.442,51.626 h1.52
  text "ADDITIONAL REQUIREMENTS:" at 714.742,47.322 h1.52
  text "MICROSECTION:" at 716.641,44.601 h1.52
  text "YES" at 739.647,44.601 h1.52
  text "REQUIRED" at 761.529,40.935 h1.52
  text "BARE BOARD ELEC. TEST:" at 716.641,40.863 h1.52
  text "NONE" at 749.807,40.863 h1.52
  text "X" at 758.532,40.863 h1.52
  text "PER ORDER" at 776.566,40.863 h1.52
  text "XX MIL VIAS REQUIRE NON-CONDUCTIVE FILL AND PLANARIZE" at 720.912,35.657 h1.5
  text "XX MIL VIAS REQUIRE CONDUCTIVE FILL AND PLANARIZE" at 721.116,33.016 h1.52
  text "OUTER XX MIL TRACES REQUIRE 50 OHM SINGLE-ENDED IMPEDANCE" at 721.091,28.866 h1.47
  text "LAYER 2 & 3 (INNER LAYERS) XX MIL WIDE, XX MIL SPACE / TRACES REQUIRE 100 OHM DIFFERENTIAL IMPEDANCE" at 720.887,22.879 h1.52
  text ".Layer_Name" at 14.656,-21.806 h1.52
M11 Gerber Information:
  lines w0.254: -7.417,-23.626 160.223,-23.626 ; -7.417,-18.462 160.274,-18.462 ; -7.417,-13.297 -7.417,-28.791 94.31,-28.791 160.274,-28.791 160.274,-13.297 -7.404,-13.297 -7.404,-28.791 32.614,-28.791 ; 55.194,-28.791 55.194,-13.297 ; 87.376,-18.462 87.376,-13.297 ; 108.712,-18.462 108.712,-13.297 ; 124.511,-28.956 124.511,-23.804
  text "ALL ARTWORK VIEWED FROM TOP SIDE" at -5.804,-16.654 h1.52
  text "BOARD #:" at 57.099,-16.654 h1.52
  text ".PRJ_Number" at 70.955,-16.654 h1.52
  text "REV:" at 92.405,-16.654 h1.52
  text ".PCB_Rev" at 99.809,-16.654 h1.52
  text "SVN REV:" at 113.69,-16.654 h1.52
  text ".VersionControl_RevNumber" at 126.543,-16.654 h1.52
  text "LAYER NAME =" at -5.804,-21.806 h1.52
  text "PLOT NAME =" at -5.804,-27.034 h1.52
  text ".plot_File_Name" at 14.656,-27.034 h1.52
  text "GENERATED    :" at 57.15,-27.034 h1.52
  text ".Print_Date" at 79.235,-27.034 h1.52
  text ".Print_Time" at 97.752,-27.034 h1.52
  text "TEXAS INSTRUMENTS" at 129.87,-27.034 h1.52
M12 Stackup:
  drawing of 191 lines, arcs and shapes, not listed
  text "Layer" at 674.469,457.523 h1.52
  text "Name" at 684.88,457.523 h1.52
  text "Material" at 708.496,457.523 h1.52
  text "Thickness" at 730.334,457.523 h1.52
  text "Constant" at 746.84,457.523 h1.52
  text "Board Layer Stack" at 761.314,457.523 h1.52
  text "Top Overlay" at 684.88,454.475 h1.52
  text "Top Solder" at 684.88,451.427 h1.52
  text "Solder Resist" at 708.496,451.427 h1.52
  text "0.40mil" at 730.334,451.427 h1.52
  text "3.5" at 746.84,451.427 h1.52
  text "1" at 674.469,448.379 h1.52
  text "Top Layer" at 684.88,448.379 h1.52
  text "1.40mil" at 730.334,448.379 h1.52
  text "Dielectric1" at 684.88,445.331 h1.52
  text "FR-4 High Tg" at 708.496,445.331 h1.52
  text "59.20mil" at 730.334,445.331 h1.52
  text "4.8" at 746.84,445.331 h1.52
  text "2" at 674.469,442.283 h1.52
  text "Bottom Layer" at 684.88,442.283 h1.52
  text "1.40mil" at 730.334,442.283 h1.52
  text "Bottom Solder" at 684.88,439.235 h1.52
  text "Solder Resist" at 708.496,439.235 h1.52
  text "0.40mil" at 730.334,439.235 h1.52
  text "3.5" at 746.84,439.235 h1.52
  text "Bottom Overlay" at 684.88,436.187 h1.52
  text ".Layer_Name" at 14.656,-21.806 h1.52
M13 Component Bodies Top:
  text ".Layer_Name" at 14.656,-21.806 h1.52
M14 Component Bodies Bottom:
  text ".Layer_Name" at 14.656,-21.806 h1.52
M15 Courtyards Top:
  text ".Layer_Name" at 14.656,-21.806 h1.52
M16 Courtyards Bottom:
  text ".Layer_Name" at 14.656,-21.806 h1.52
Drill Drawing:
  circle w0.254: c144.112,83.421 r0.702
  lines w0.254: 143.411,79.561 144.814,79.561 144.814,80.965 143.411,80.965 143.411,79.561
  lines w0.305: 142.138,78.614 224.218,78.614 ; 142.138,84.929 224.218,84.929 ; 150.72,75.456 150.72,88.087 ; 159.153,75.456 159.153,88.087 ; 175.322,75.456 175.322,88.087 ; 181.904,75.456 181.904,88.087 ; 191.433,75.456 191.433,88.087 ; 209.831,75.456 209.831,88.087 ; 142.138,75.456 224.218,75.456 224.218,88.087 142.138,88.087 142.138,75.456
  text "Symbol" at 144.033,85.877 h1.83
  text "Quantity" at 151.667,85.877 h1.83
  text "Finished Hole Size" at 160.1,85.877 h1.83
  text "Plated" at 176.269,85.877 h1.83
  text "Hole Type" at 182.851,85.877 h1.83
  text "Drill Layer Pair" at 192.38,85.877 h1.83
  text "Hole Tolerance" at 210.778,85.877 h1.83
  text "3" at 151.667,82.719 h1.52
  text "11.81mil (0.300mm)" at 160.1,82.719 h1.52
  text "PTH" at 176.269,82.719 h1.52
  text "Round" at 182.851,82.719 h1.52
  text "Top Layer - Bottom Layer" at 192.38,82.719 h1.52
  text "3" at 151.667,79.561 h1.52
  text "19.69mil (0.500mm)" at 160.1,79.561 h1.52
  text "PTH" at 176.269,79.561 h1.52
  text "Round" at 182.851,79.561 h1.52
  text "Top Layer - Bottom Layer" at 192.38,79.561 h1.52
  text "6 Total" at 151.667,76.404 h1.52
  text ".Layer_Name" at 14.656,-21.806 h1.52
M17 Embedded Cavity:
  text ".Layer_Name" at 14.656,-21.806 h1.52
M18 Embedded Assembly:
  text ".Layer_Name" at 14.656,-21.806 h1.52
M19 Embedded Keepout:
  text ".Layer_Name" at 14.91,-21.552 h1.52

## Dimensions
0,-10.16 to 25.4,-10.16 on M2 Board Dimensions
0,0 to 10,0 on M2 Board Dimensions
0,0 to 0,15 on M2 Board Dimensions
